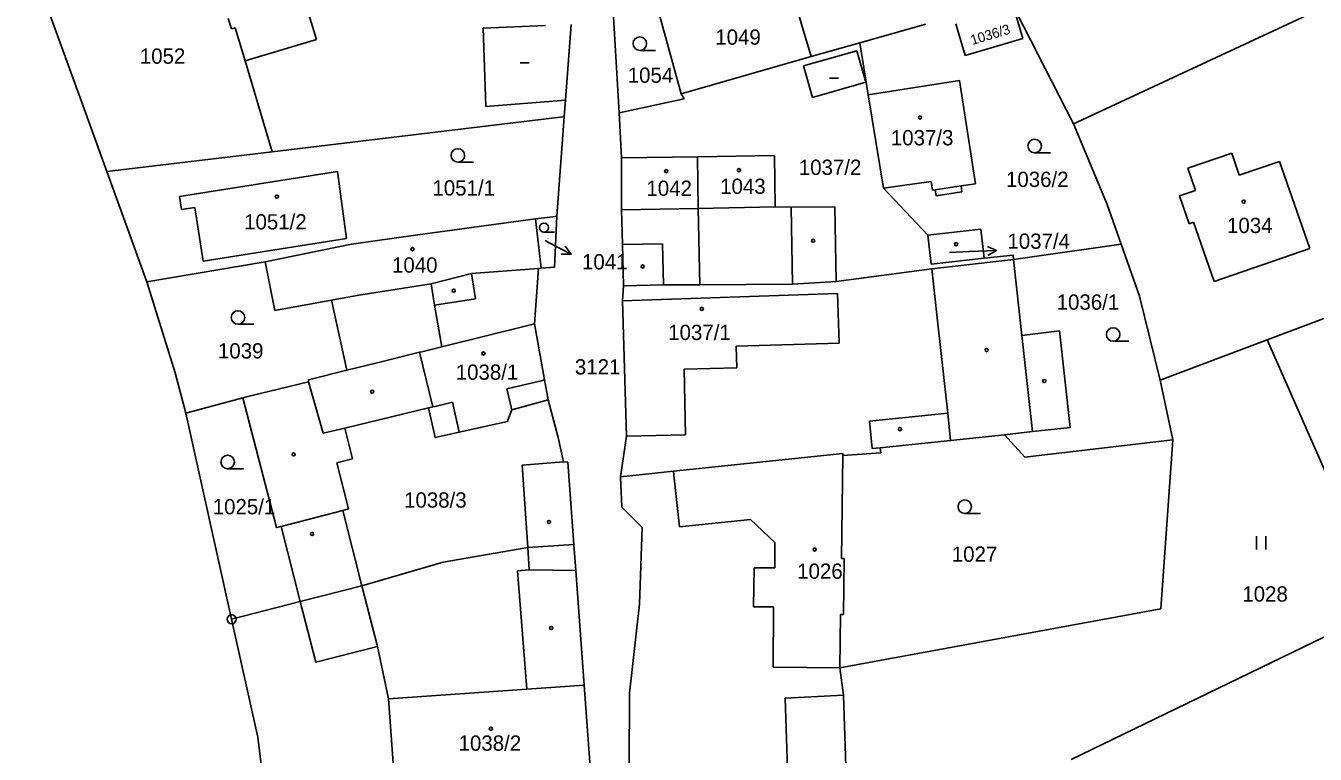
# Model space of a CAD drawing. Extents: x -736345 to -729997, y -1130177 to -1122501.
# Drawn here: x -733625.7 to -733482.4, y -1127121.9 to -1127040.9 of the extents above; entities that cross this region are included whole.
import ezdxf

# ---------------------------------------------------------------- set-up
doc = ezdxf.new("R2010")
doc.units = 0
for name, color, linetype in [('Vrstva 1', 7, 'Continuous'), ('Vrstva 16', 7, 'Continuous'), ('Vrstva 18', 7, 'Continuous'), ('Vrstva 19', 7, 'Continuous'), ('Vrstva 25', 7, 'Continuous'), ('Vrstva 4', 7, 'Continuous')]:
    doc.layers.add(name, color=color, linetype=linetype)

msp = doc.modelspace()

# ---------------------------------------------------------------- linework, layer by layer
at = {"layer": 'Vrstva 1'}
for points in [[(-733625.68, -1127032.29), (-733619.21, -1127050.13)], [(-733472.14, -1127034.5), (-733508.86, -1127051.61)], [(-733540.57, -1127037.09), (-733538.42, -1127044.31)], [(-733509.26, -1127051.8), (-733516.37, -1127037.89)], [(-733515.95, -1127038.8), (-733514.9, -1127042.32)], [(-733603.19, -1127040.09), (-733602.84, -1127041.25)], [(-733559.75, -1127050.58), (-733560.41, -1127039.29)], [(-733552.86, -1127048.48), (-733555.4, -1127039.19)], [(-733602.84, -1127041.25), (-733602.41, -1127041.13)], [(-733602.41, -1127041.13), (-733601.32, -1127044.81)], [(-733565.08, -1127040.77), (-733565.71, -1127049.18)], [(-733525.66, -1127040.73), (-733533.01, -1127042.82)], [(-733521.29, -1127044.23), (-733522.34, -1127040.71)], [(-733538.42, -1127044.31), (-733533.01, -1127042.82)], [(-733533.01, -1127042.82), (-733532.07, -1127048.58)], [(-733514.9, -1127042.32), (-733521.29, -1127044.23)], [(-733601.32, -1127044.81), (-733598.3, -1127054.92)], [(-733538.42, -1127044.31), (-733552.86, -1127048.48)], [(-733532.07, -1127048.58), (-733521.95, -1127046.99)], [(-733521.95, -1127046.99), (-733520.15, -1127058.47)], [(-733565.71, -1127049.18), (-733565.81, -1127050.56)], [(-733559.75, -1127050.58), (-733552.53, -1127049.03)], [(-733552.53, -1127049.03), (-733552.86, -1127048.48)], [(-733530.37, -1127058.95), (-733532.07, -1127048.58)], [(-733619.21, -1127050.13), (-733616.67, -1127057.12)], [(-733565.81, -1127050.56), (-733565.85, -1127051.03)], [(-733559.5, -1127055.59), (-733559.75, -1127050.58)], [(-733566.3, -1127051.08), (-733584.16, -1127053.23)], [(-733565.85, -1127051.03), (-733566.67, -1127062.07)], [(-733565.85, -1127051.03), (-733566.3, -1127051.08)], [(-733508.86, -1127051.61), (-733509.26, -1127051.8)], [(-733506.64, -1127058.12), (-733509.26, -1127051.8)], [(-733598.3, -1127054.92), (-733584.16, -1127053.23)], [(-733616.67, -1127057.12), (-733598.3, -1127054.92)], [(-733559.5, -1127055.59), (-733551.06, -1127055.46)], [(-733559.49, -1127061.37), (-733559.5, -1127055.59)], [(-733551.06, -1127055.46), (-733542.5, -1127055.33)], [(-733550.96, -1127061.21), (-733551.06, -1127055.46)], [(-733542.5, -1127055.33), (-733542.41, -1127061.04)], [(-733496.58, -1127056.73), (-733491.69, -1127055.07)], [(-733491.69, -1127055.07), (-733490.85, -1127057.53)], [(-733490.85, -1127057.53), (-733486.37, -1127056.01)], [(-733486.37, -1127056.01), (-733483.01, -1127065.65)], [(-733616.67, -1127057.12), (-733612.22, -1127069.36)], [(-733608.61, -1127059.89), (-733591.04, -1127057.11)], [(-733591.04, -1127057.11), (-733590.04, -1127064.57)], [(-733495.71, -1127059.22), (-733496.58, -1127056.73)], [(-733525.07, -1127058.21), (-733530.37, -1127058.95)], [(-733530.37, -1127058.95), (-733525.44, -1127064.17)], [(-733524.92, -1127059.19), (-733525.07, -1127058.21)], [(-733524.62, -1127059.14), (-733524.92, -1127059.19)], [(-733524.51, -1127059.8), (-733524.62, -1127059.14)], [(-733520.15, -1127058.47), (-733521.76, -1127058.7)], [(-733521.76, -1127058.7), (-733521.66, -1127059.36)], [(-733505.54, -1127060.77), (-733506.64, -1127058.12)], [(-733497.48, -1127059.83), (-733495.71, -1127059.22)], [(-733608.39, -1127061.32), (-733608.61, -1127059.89)], [(-733521.66, -1127059.36), (-733524.51, -1127059.8)], [(-733496.4, -1127062.92), (-733497.48, -1127059.83)], [(-733606.9, -1127061.09), (-733608.39, -1127061.32)], [(-733605.96, -1127067.07), (-733606.9, -1127061.09)], [(-733567.12, -1127062.13), (-733566.67, -1127062.07)], [(-733566.67, -1127062.07), (-733566.94, -1127067.73)], [(-733559.37, -1127065.23), (-733559.49, -1127061.37)], [(-733550.96, -1127061.21), (-733550.8, -1127069.69)], [(-733542.41, -1127061.04), (-733540.64, -1127061.06)], [(-733540.64, -1127061.06), (-733540.49, -1127069.64)], [(-733503.96, -1127065.2), (-733505.54, -1127060.77)], [(-733582.11, -1127064.15), (-733569.06, -1127062.36)], [(-733569.06, -1127062.36), (-733567.12, -1127062.13)], [(-733569.06, -1127062.36), (-733568.43, -1127067.85)], [(-733525.44, -1127064.17), (-733519.55, -1127063.51)], [(-733519.55, -1127063.51), (-733519.18, -1127066.75)], [(-733495.92, -1127062.75), (-733496.4, -1127062.92)], [(-733493.62, -1127069.34), (-733495.92, -1127062.75)], [(-733487.76, -1127075.82), (-733451.83, -1127062.31)], [(-733590.04, -1127064.57), (-733605.96, -1127067.07)], [(-733589.5, -1127065.17), (-733582.11, -1127064.15)], [(-733525.08, -1127067.41), (-733525.44, -1127064.17)], [(-733599.09, -1127067.15), (-733589.5, -1127065.17)], [(-733559.27, -1127069.81), (-733559.37, -1127065.23)], [(-733519.18, -1127066.75), (-733515.98, -1127066.39)], [(-733515.98, -1127066.39), (-733515.92, -1127066.89)], [(-733515.92, -1127066.89), (-733503.96, -1127065.2)], [(-733501.92, -1127070.95), (-733503.96, -1127065.2)], [(-733483.01, -1127065.65), (-733493.62, -1127069.34)], [(-733612.22, -1127069.36), (-733599.09, -1127067.15)], [(-733599.09, -1127067.15), (-733598.02, -1127072.54)], [(-733566.94, -1127067.73), (-733568.43, -1127067.85)], [(-733519.18, -1127066.75), (-733525.08, -1127067.41)], [(-733515.92, -1127066.89), (-733525.02, -1127067.91)], [(-733515.01, -1127075.34), (-733515.92, -1127066.89)], [(-733568.72, -1127067.88), (-733569.16, -1127074.05)], [(-733568.43, -1127067.85), (-733568.72, -1127067.88)], [(-733535.63, -1127069.35), (-733525.02, -1127067.91)], [(-733609.07, -1127079.48), (-733612.22, -1127069.36)], [(-733559.38, -1127071.49), (-733559.27, -1127069.81)], [(-733554.82, -1127069.71), (-733559.27, -1127069.81)], [(-733550.8, -1127069.69), (-733554.82, -1127069.71)], [(-733540.49, -1127069.64), (-733550.8, -1127069.69)], [(-733535.63, -1127069.35), (-733540.49, -1127069.64)], [(-733598.02, -1127072.54), (-733591.73, -1127071.42)], [(-733591.73, -1127071.42), (-733590.01, -1127079.19)], [(-733558.93, -1127086.52), (-733559.38, -1127071.49)], [(-733499.64, -1127080.3), (-733501.92, -1127070.95)], [(-733579.47, -1127076.59), (-733569.74, -1127074.2)], [(-733569.74, -1127074.2), (-733569.16, -1127074.05)], [(-733569.16, -1127074.05), (-733569.09, -1127074.44)], [(-733569.09, -1127074.44), (-733568.05, -1127080.27)], [(-733510.82, -1127074.82), (-733515.01, -1127075.34)], [(-733509.62, -1127085.58), (-733510.82, -1127074.82)], [(-733499.64, -1127080.3), (-733487.76, -1127075.82)], [(-733487.76, -1127075.82), (-733487.32, -1127076.82)], [(-733586.8, -1127078.4), (-733581.93, -1127077.2)], [(-733581.93, -1127077.2), (-733581.67, -1127077.14)], [(-733581.93, -1127077.2), (-733580.47, -1127083.27)], [(-733581.67, -1127077.14), (-733579.47, -1127076.59)], [(-733487.32, -1127076.82), (-733478.92, -1127095.84)], [(-733594.27, -1127080.25), (-733590.01, -1127079.19)], [(-733590.01, -1127079.19), (-733586.8, -1127078.4)], [(-733607.9, -1127083.97), (-733609.07, -1127079.48)], [(-733594.25, -1127080.49), (-733600.99, -1127082.1)], [(-733594.25, -1127080.49), (-733594.27, -1127080.25)], [(-733568.05, -1127080.27), (-733567.65, -1127082.47)], [(-733498.24, -1127086.93), (-733499.64, -1127080.3)], [(-733601.57, -1127082.26), (-733600.99, -1127082.1)], [(-733607.9, -1127083.97), (-733601.57, -1127082.26)], [(-733601.57, -1127082.26), (-733597.81, -1127096.69), (-733597.31, -1127096.56)], [(-733580.47, -1127083.27), (-733580.92, -1127083.38)], [(-733580.92, -1127083.38), (-733580.18, -1127086.68), (-733577.54, -1127086.09)], [(-733571.67, -1127083.61), (-733567.65, -1127082.47)], [(-733567.65, -1127082.47), (-733566.51, -1127086.69)], [(-733602.81, -1127106.87), (-733607.9, -1127083.97)], [(-733577.54, -1127086.09), (-733573.34, -1127085.15), (-733572.16, -1127084.89), (-733572.07, -1127084.65), (-733571.67, -1127083.61)], [(-733516.94, -1127086.36), (-733522.94, -1127086.99)], [(-733516.94, -1127086.36), (-733513.81, -1127086.02)], [(-733514.69, -1127088.86), (-733516.94, -1127086.36)], [(-733513.81, -1127086.02), (-733509.62, -1127085.58)], [(-733566.51, -1127086.69), (-733565.94, -1127089.38)], [(-733559.59, -1127091.03), (-733558.93, -1127086.52)], [(-733530.75, -1127087.81), (-733522.94, -1127086.99)], [(-733530.69, -1127088.39), (-733530.75, -1127087.81)], [(-733498.24, -1127086.93), (-733514.69, -1127088.86)], [(-733499.57, -1127105.73), (-733498.24, -1127086.93)], [(-733553.72, -1127090.41), (-733534.9, -1127088.45)], [(-733534.91, -1127088.69), (-733535.06, -1127100.12)], [(-733534.91, -1127088.69), (-733530.69, -1127088.39)], [(-733534.9, -1127088.45), (-733534.91, -1127088.69)], [(-733565.94, -1127089.38), (-733565.44, -1127089.4)], [(-733565.44, -1127089.4), (-733564.78, -1127098.58)], [(-733553.72, -1127090.41), (-733559.59, -1127091.03)], [(-733559.46, -1127094.43), (-733559.59, -1127091.03)], [(-733557.2, -1127096.67), (-733559.46, -1127094.43)], [(-733595.18, -1127104.92), (-733597.31, -1127096.56)], [(-733557.49, -1127105.19), (-733557.2, -1127096.67)], [(-733579.29, -1127100.53), (-733569.91, -1127098.91)], [(-733569.91, -1127098.91), (-733564.78, -1127098.58)], [(-733564.57, -1127101.47), (-733564.78, -1127098.58)], [(-733588.33, -1127103.17), (-733579.29, -1127100.53)], [(-733535.06, -1127100.12), (-733534.75, -1127100.13)], [(-733534.75, -1127100.13), (-733534.81, -1127106.34)], [(-733563.64, -1127114.2), (-733564.57, -1127101.47)], [(-733595.18, -1127104.92), (-733588.33, -1127103.17)], [(-733602.81, -1127106.87), (-733595.18, -1127104.92)], [(-733595.18, -1127104.92), (-733593.46, -1127111.66)], [(-733558.61, -1127115.09), (-733557.49, -1127105.19)], [(-733535.23, -1127112.28), (-733499.57, -1127105.73)], [(-733535.15, -1127106.34), (-733535.23, -1127112.28)], [(-733534.81, -1127106.34), (-733535.15, -1127106.34)], [(-733599.9, -1127120), (-733602.81, -1127106.87)], [(-733479.17, -1127107.75), (-733509.52, -1127122.48)], [(-733593.46, -1127111.66), (-733586.61, -1127109.92)], [(-733585.36, -1127115.73), (-733586.61, -1127109.92)], [(-733534.83, -1127115.31), (-733535.23, -1127112.28)], [(-733562.91, -1127124.29), (-733563.64, -1127114.2)], [(-733558.66, -1127130.98), (-733558.61, -1127115.09)], [(-733585.36, -1127115.73), (-733584.65, -1127125.9)], [(-733534.24, -1127133.41), (-733534.83, -1127115.31)], [(-733598.44, -1127131.82), (-733599.9, -1127120)]]:
    msp.add_lwpolyline(points, dxfattribs=at)
at = {"layer": 'Vrstva 16'}
for points in [[(-733567.97, -1127064.79), (-733567.74, -1127064.9)], [(-733523.03, -1127066.1), (-733520.81, -1127066.01)]]:
    msp.add_lwpolyline(points, dxfattribs=at)
at = {"layer": 'Vrstva 25'}
for points in [[(-733557.45, -1127043.64), (-733555.7, -1127043.64)], [(-733570.76, -1127045.02), (-733569.76, -1127045.02)], [(-733536.38, -1127046.74), (-733535.38, -1127046.74)], [(-733577.68, -1127056.07), (-733575.93, -1127056.07)], [(-733513.59, -1127055.02), (-733511.84, -1127055.02)], [(-733568.11, -1127063.86), (-733566.937, -1127063.86)], [(-733567.74, -1127064.91), (-733565.079, -1127066.295)], [(-733565.736, -1127065.389), (-733565.079, -1127066.295), (-733566.197, -1127066.277)], [(-733520.81, -1127066.01), (-733517.813, -1127065.895)], [(-733518.831, -1127065.434), (-733517.813, -1127065.895), (-733518.793, -1127066.432)], [(-733602.1, -1127074.09), (-733600.35, -1127074.09)], [(-733504.86, -1127075.98), (-733503.11, -1127075.98)], [(-733603.25, -1127090.15), (-733601.5, -1127090.15)], [(-733521.35, -1127095.11), (-733519.6, -1127095.11)], [(-733488.917, -1127099.125), (-733488.917, -1127097.625)], [(-733487.883, -1127099.125), (-733487.883, -1127097.625)]]:
    msp.add_lwpolyline(points, dxfattribs=at)
for centre, radius in [((-733557.45, -1127042.89), 0.75), ((-733526.33, -1127051.1), 0.175), ((-733577.68, -1127055.32), 0.75), ((-733513.59, -1127054.27), 0.75), ((-733554.52, -1127057.07), 0.175), ((-733546.44, -1127056.96), 0.175), ((-733597.78, -1127059.9), 0.175), ((-733490.35, -1127060.45), 0.175), ((-733568.11, -1127063.357), 0.503), ((-733538.19, -1127064.8), 0.175), ((-733582.71, -1127065.74), 0.175), ((-733522.31, -1127065.18), 0.175), ((-733557.14, -1127067.67), 0.175), ((-733578.13, -1127070.36), 0.175), ((-733602.1, -1127073.34), 0.75), ((-733550.56, -1127072.38), 0.175), ((-733504.86, -1127075.23), 0.75), ((-733574.83, -1127077.34), 0.175), ((-733518.92, -1127076.94), 0.175), ((-733512.52, -1127080.39), 0.175), ((-733587.19, -1127081.57), 0.175), ((-733528.55, -1127085.74), 0.175), ((-733603.25, -1127089.4), 0.75), ((-733595.92, -1127088.55), 0.175), ((-733521.35, -1127094.36), 0.75), ((-733567.55, -1127096.06), 0.175), ((-733593.87, -1127097.4), 0.175), ((-733538.03, -1127099.12), 0.175), ((-733602.81, -1127106.87), 0.5), ((-733602.81, -1127106.87), 0.032), ((-733567.31, -1127107.85), 0.175), ((-733574, -1127119.05), 0.175)]:
    msp.add_circle(centre, radius, dxfattribs=at)
at = {"layer": 'Vrstva 4'}
for points in [[(-733594.4, -1127039.08), (-733593.38, -1127042.45)], [(-733574.87, -1127041.18), (-733567.93, -1127040.89)], [(-733574.58, -1127049.89), (-733574.87, -1127041.18)], [(-733593.38, -1127042.45), (-733601.32, -1127044.81)], [(-733539.28, -1127045.37), (-733533.33, -1127043.68)], [(-733533.33, -1127043.68), (-733532.33, -1127047.19)], [(-733539.28, -1127045.37), (-733538.28, -1127048.88)], [(-733532.33, -1127047.19), (-733538.28, -1127048.88)], [(-733565.71, -1127049.18), (-733574.58, -1127049.89)], [(-733524.62, -1127059.14), (-733521.76, -1127058.7)], [(-733559.49, -1127061.37), (-733550.96, -1127061.21)], [(-733550.96, -1127061.21), (-733542.41, -1127061.04)], [(-733540.64, -1127061.06), (-733535.77, -1127061.02)], [(-733535.77, -1127061.02), (-733535.63, -1127069.35)], [(-733559.37, -1127065.23), (-733554.92, -1127065.14)], [(-733554.92, -1127065.14), (-733554.82, -1127069.71)], [(-733580.64, -1127069.61), (-733576.14, -1127068.46)], [(-733576.14, -1127068.46), (-733569.22, -1127067.92)], [(-733576.14, -1127068.46), (-733575.71, -1127071.27)], [(-733569.22, -1127067.92), (-733568.72, -1127067.88)], [(-733525.02, -1127067.91), (-733524.45, -1127073.04)], [(-733588.66, -1127070.87), (-733580.64, -1127069.61)], [(-733580.27, -1127071.98), (-733580.64, -1127069.61)], [(-733535.49, -1127070.68), (-733559.38, -1127071.49)], [(-733535.38, -1127073.95), (-733535.49, -1127070.68)], [(-733591.73, -1127071.42), (-733588.66, -1127070.87)], [(-733575.71, -1127071.27), (-733580.27, -1127071.98)], [(-733580.27, -1127071.98), (-733579.47, -1127076.59)], [(-733524.45, -1127073.04), (-733523.22, -1127083.98)], [(-733535.38, -1127073.95), (-733535.3, -1127076.2)], [(-733535.3, -1127076.2), (-733546.75, -1127076.53)], [(-733515.01, -1127075.34), (-733513.81, -1127086.02)], [(-733546.75, -1127076.53), (-733546.68, -1127078.94)], [(-733546.68, -1127078.94), (-733552.54, -1127079.08)], [(-733552.54, -1127079.08), (-733552.37, -1127086.37)], [(-733592.64, -1127086.21), (-733594.25, -1127080.49)], [(-733572.22, -1127081.28), (-733568.42, -1127080.36)], [(-733568.42, -1127080.36), (-733568.05, -1127080.27)], [(-733571.67, -1127083.61), (-733572.22, -1127081.28)], [(-733580.92, -1127083.38), (-733590.23, -1127085.63)], [(-733580.21, -1127083.21), (-733580.47, -1127083.27)], [(-733580.21, -1127083.21), (-733578.27, -1127082.74)], [(-733578.27, -1127082.74), (-733577.54, -1127086.09)], [(-733523.22, -1127083.98), (-733531.95, -1127084.85)], [(-733531.95, -1127084.85), (-733531.65, -1127087.91)], [(-733523.22, -1127083.98), (-733522.94, -1127086.99)], [(-733590.23, -1127085.63), (-733592.64, -1127086.21)], [(-733590.23, -1127085.63), (-733589.39, -1127089.03), (-733591.11, -1127089.49), (-733589.81, -1127094.6), (-733590.46, -1127094.77)], [(-733552.37, -1127086.37), (-733558.93, -1127086.52)], [(-733531.65, -1127087.91), (-733530.75, -1127087.81)], [(-733565.94, -1127089.38), (-733570.53, -1127089.73)], [(-733570.53, -1127089.73), (-733569.91, -1127098.91)], [(-733553.67, -1127090.86), (-733553.72, -1127090.41)], [(-733553.03, -1127096.6), (-733553.67, -1127090.86)], [(-733597.31, -1127096.56), (-733590.46, -1127094.77)], [(-733590.46, -1127094.77), (-733588.33, -1127103.17)], [(-733545.16, -1127095.79), (-733553.03, -1127096.6)], [(-733542.47, -1127098.36), (-733545.16, -1127095.79)], [(-733569.91, -1127098.91), (-733569.74, -1127101.4)], [(-733542.44, -1127101.15), (-733542.47, -1127098.36)], [(-733569.74, -1127101.4), (-733571.03, -1127101.49)], [(-733571.03, -1127101.49), (-733570.02, -1127114.65)], [(-733569.74, -1127101.4), (-733564.57, -1127101.47)], [(-733544.82, -1127105.49), (-733544.76, -1127101.17)], [(-733544.76, -1127101.17), (-733542.44, -1127101.15)], [(-733586.61, -1127109.92), (-733588.33, -1127103.17)], [(-733542.6, -1127105.5), (-733544.82, -1127105.49)], [(-733542.65, -1127112.2), (-733542.6, -1127105.5)], [(-733535.23, -1127112.28), (-733542.65, -1127112.2)], [(-733570.02, -1127114.65), (-733585.36, -1127115.73)], [(-733570.02, -1127114.65), (-733563.64, -1127114.2)], [(-733534.83, -1127115.31), (-733541.3, -1127115.63)], [(-733541.3, -1127115.63), (-733540.71, -1127133.62)]]:
    msp.add_lwpolyline(points, dxfattribs=at)

# ---------------------------------------------------------------- texts
at = {"layer": 'Vrstva 16'}
for s, p in [('1037/4', (-733516.61, -1127065.7)), ('1041', (-733563.88, -1127067.99))]:
    msp.add_text(s, height=1.7, dxfattribs=at).set_placement(p)
at = {"layer": 'Vrstva 18'}
for s, height, p in [('1052', 1.7, (-733613.01, -1127045.13)), ('1054', 1.7, (-733558.8, -1127047.25)), ('1036/2', 1.7, (-733516.77, -1127058.83)), ('1051/1', 1.7, (-733580.5, -1127059.78)), ('1041', 0.1, (-733567.77, -1127064.59)), ('1036/1', 1.7, (-733511.14, -1127072.47)), ('1039', 1.7, (-733604.33, -1127077.89)), ('3121', 1.7, (-733564.67, -1127079.67)), ('1025/1', 1.7, (-733604.91, -1127095.21)), ('1027', 1.7, (-733522.79, -1127100.49)), ('1028', 1.7, (-733490.51, -1127104.91))]:
    msp.add_text(s, height=height, dxfattribs=at).set_placement(p)
at = {"layer": 'Vrstva 19'}
for s, height, p in [('1049', 1.7, (-733549.07, -1127043.02)), ('1037/3', 1.7, (-733529.56, -1127054.2)), ('1037/2', 1.7, (-733539.79, -1127057.49)), ('1042', 1.7, (-733556.72, -1127059.82)), ('1043', 1.7, (-733548.53, -1127059.6)), ('1051/2', 1.7, (-733601.42, -1127063.55)), ('1034', 1.7, (-733492.21, -1127063.95)), ('1037/4', 0.1, (-733522.83, -1127065.9)), ('1040', 1.7, (-733584.99, -1127068.35)), ('1037/1', 1.7, (-733554.3, -1127075.84)), ('1038/1', 1.7, (-733577.91, -1127080.26)), ('1038/3', 1.7, (-733583.648, -1127094.47)), ('1026', 1.7, (-733539.97, -1127102.38)), ('1038/2', 1.7, (-733577.59, -1127121.49))]:
    msp.add_text(s, height=height, dxfattribs=at).set_placement(p)
msp.add_text('1036/3', height=1.1, rotation=16.90013, dxfattribs=at).set_placement((-733520.507, -1127043.061))

doc.saveas('drawing.dxf')
